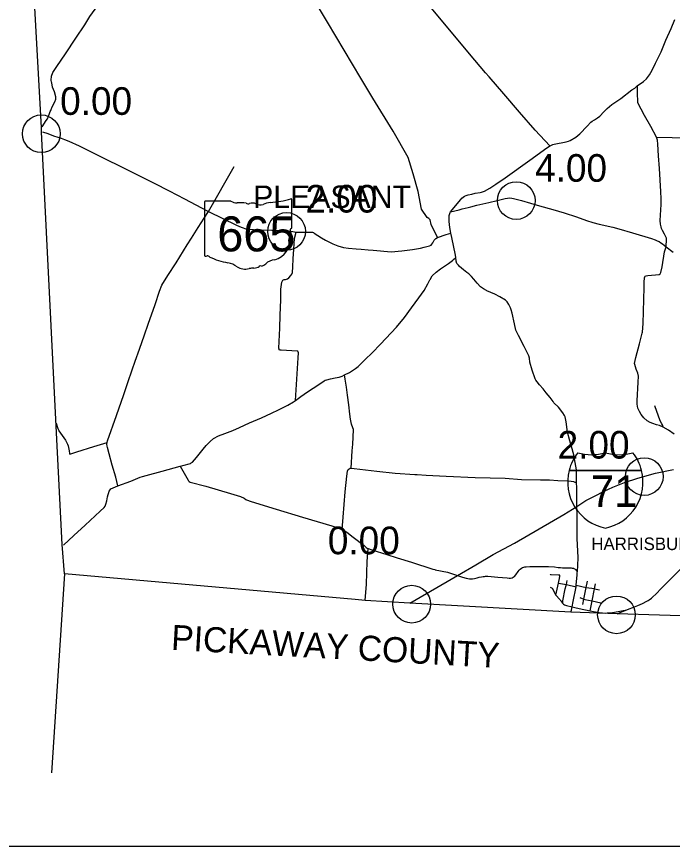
# Model space of a CAD drawing. Extents: x 1659811 to 1934326, y 644115 to 934867.
# Drawn here: x 1757686 to 1783780, y 650175 to 683194 of the extents above; entities that cross this region are included whole.
import ezdxf

# ---------------------------------------------------------------- set-up
doc = ezdxf.new("R2010")
doc.units = 0
for name, color, linetype in [('Default', 7, 'Continuous'), ('GM_X_Adjacent_County', 7, 'Continuous'), ('GM_X_Adjacent_County_Text', 7, 'Continuous'), ('GM_X_City_Street', 7, 'Continuous'), ('GM_X_Corporation_Text', 7, 'Continuous'), ('GM_X_County', 7, 'Continuous'), ('GM_X_County_Road', 7, 'Continuous'), ('GM_X_Interstate_Route', 7, 'Continuous'), ('GM_X_Interstate_Shield', 7, 'Continuous'), ('GM_X_State_Route', 7, 'Continuous'), ('GM_X_State_Shield', 7, 'Continuous'), ('GM_X_Township_Road', 7, 'Continuous'), ('GM_X_Township_Text', 7, 'Continuous'), ('GM_X_US_Route', 7, 'Continuous'), ('SC_Scratch1', 7, 'Continuous')]:
    doc.layers.add(name, color=color, linetype=linetype)

msp = doc.modelspace()

# ---------------------------------------------------------------- linework, layer by layer
at = {"layer": 'Default'}
for centre in [(1758669, 678534), (1758669, 678534), (1777567, 675872), (1768427, 674646), (1782661, 664892), (1773406, 659814), (1773406, 659814), (1781555, 659388), (1781555, 659388)]:
    msp.add_circle(centre, 750, dxfattribs=at)
at = {"layer": 'GM_X_Adjacent_County'}
msp.add_line((1759596, 661027), (1759070, 653104), dxfattribs=at)
at = {"layer": 'GM_X_City_Street'}
for points in [[(1779847, 661240), (1779853, 661239), (1779883, 661223), (1779909, 661206), (1779930, 661187), (1779979, 661133), (1780000, 661107)], [(1778915, 660978), (1778930, 660991), (1778950, 660994), (1779248, 660981), (1779262, 660981), (1779284, 660976)], [(1779263, 660711), (1779287, 660836), (1779305, 660926), (1779302, 660952), (1779284, 660976)], [(1779551, 660558), (1779561, 660595), (1779563, 660601), (1779594, 660760)], [(1779741, 659492), (1779762, 659575), (1779789, 659710), (1779832, 659924), (1779945, 660504), (1779955, 660564), (1779994, 660984), (1779997, 661054)], [(1780218, 659794), (1780262, 660012), (1780354, 660480), (1780407, 660730)], [(1778914, 660484), (1778995, 660444), (1779147, 660174), (1779301, 659998), (1779316, 659981)], [(1779147, 660174), (1779218, 660526), (1779253, 660654), (1779263, 660711)], [(1779253, 660654), (1779413, 660623)], [(1779413, 660623), (1779561, 660595), (1779945, 660504)], [(1779413, 659848), (1779419, 659887), (1779421, 659949), (1779516, 660426), (1779551, 660558)], [(1779955, 660564), (1780354, 660480), (1780676, 660432)], [(1780506, 659550), (1780588, 659944), (1780679, 660419)], [(1780676, 660432), (1780676, 660432), (1780681, 660430), (1780880, 660384)], [(1780679, 660419), (1780680, 660423), (1780681, 660430), (1780720, 660624)], [(1780101, 660073), (1780262, 660012), (1780292, 660006)], [(1779316, 659981), (1779328, 659966), (1779352, 659929), (1779378, 659888), (1779413, 659848)], [(1779413, 659848), (1779453, 659809), (1779488, 659785), (1779561, 659760), (1779789, 659710)], [(1780292, 660006), (1780588, 659944), (1780937, 659869)], [(1779789, 659710), (1779892, 659678), (1780069, 659640), (1780506, 659550), (1780854, 659487), (1780872, 659483)]]:
    msp.add_lwpolyline(points, dxfattribs=at)
at = {"layer": 'GM_X_County'}
msp.add_lwpolyline([(1784956, 659328), (1781576, 659434), (1779741, 659492), (1773339, 659850), (1771560, 659962), (1771157, 659994), (1759596, 661027), (1759497, 662188), (1759258, 666902), (1758681, 678614), (1758672, 678766), (1758400, 683790), (1758170, 688397), (1758072, 690399), (1757841, 694414), (1757825, 694698), (1757564, 699226), (1758151, 699596), (1759102, 700215)], dxfattribs=at)
at = {"layer": 'GM_X_County_Road'}
for points in [[(1759077, 680590), (1759061, 680668), (1759078, 680818), (1759131, 680968), (1759287, 681203), (1759631, 681711), (1760047, 682335), (1760404, 682872), (1760596, 683193), (1760806, 683496), (1760873, 683608), (1761094, 683872), (1761429, 684371), (1761902, 685082), (1762236, 685589), (1762361, 685777), (1762710, 686270), (1762844, 686434), (1763167, 686851), (1763522, 687306), (1763867, 687757), (1764291, 688315), (1764315, 688347)], [(1778904, 678047), (1778314, 678671), (1777693, 679394), (1777072, 680120), (1776484, 680798), (1776345, 680960), (1775913, 681464), (1774048, 683702), (1773810, 683978), (1773735, 684084)], [(1774956, 675429), (1775362, 675913), (1775404, 675965), (1775460, 676012), (1775514, 676048), (1775572, 676079), (1775656, 676108), (1775793, 676134), (1775936, 676163), (1776130, 676195), (1776187, 676207), (1776227, 676216), (1776304, 676244), (1776516, 676373), (1776754, 676520), (1777127, 676778), (1778110, 677485), (1778787, 677975), (1778847, 678015), (1778904, 678047), (1778937, 678067), (1778976, 678084), (1779027, 678103), (1779075, 678117), (1779556, 678216), (1779642, 678244), (1779710, 678267), (1779941, 678398), (1780096, 678528), (1780393, 678836), (1780538, 679000), (1780582, 679037), (1780675, 679091), (1780795, 679160), (1780886, 679237), (1781055, 679404), (1781184, 679531), (1781374, 679692), (1781486, 679771), (1781728, 679931), (1782163, 680280), (1782279, 680349), (1782391, 680450), (1782493, 680516), (1782627, 680609), (1782752, 680718), (1782868, 680877), (1782977, 681061), (1783111, 681340), (1783339, 681797), (1783524, 682256), (1783728, 682725), (1783880, 683080)], [(1759063, 679504), (1759105, 679598), (1759208, 679807), (1759243, 679915), (1759244, 680001), (1759197, 680198), (1759119, 680391), (1759084, 680555), (1759077, 680590)], [(1783844, 666582), (1783619, 666732), (1783419, 666860), (1783270, 666922), (1783149, 666951), (1783002, 666997), (1782890, 667046), (1782780, 667109), (1782641, 667230), (1782535, 667360), (1782467, 667486), (1782408, 667615), (1782384, 667769), (1782377, 667901), (1782412, 668652), (1782429, 668886), (1782404, 669000), (1782343, 669165), (1782281, 669354), (1782273, 669384), (1782325, 669630), (1782473, 670172), (1782582, 670601), (1782588, 670635), (1782611, 670984), (1782644, 671937), (1782659, 672414), (1782657, 672628), (1782664, 672804), (1782683, 672840), (1782701, 672870), (1782735, 672884), (1782799, 672895), (1783258, 672938), (1783298, 672959), (1783324, 673007), (1783374, 673235), (1783468, 673837), (1783535, 674036), (1783550, 674333), (1783542, 674374), (1783468, 674540), (1783387, 674689), (1783347, 674762), (1783328, 674832), (1783304, 674932), (1783299, 675075), (1783336, 675721), (1783338, 675938), (1783324, 676240), (1783261, 677156), (1783230, 677651), (1783198, 678124), (1783187, 678273), (1783142, 678403), (1782923, 678824), (1782676, 679262), (1782411, 679769), (1782409, 679811), (1782392, 680130), (1782391, 680450)], [(1758707, 678813), (1758861, 679055), (1758919, 679123), (1758993, 679335), (1759023, 679416), (1759045, 679464), (1759063, 679504)], [(1783142, 678403), (1783772, 678383), (1783773, 678383)], [(1783773, 678383), (1785029, 678344), (1785034, 678343), (1785035, 678343)], [(1761718, 664522), (1761629, 664869), (1761494, 665341), (1761375, 665791), (1761303, 666042), (1761289, 666098), (1761282, 666179), (1761289, 666249), (1761307, 666319), (1761667, 667325), (1761951, 668157), (1762115, 668630), (1762282, 669135), (1762409, 669489), (1762581, 669962), (1762769, 670526), (1762924, 670951), (1763200, 671744), (1763378, 672275), (1763468, 672511), (1763705, 672898), (1764033, 673400), (1764187, 673633), (1764477, 674115), (1764641, 674378), (1764908, 674799), (1765145, 675172), (1765320, 675443)], [(1775143, 673702), (1775006, 674406), (1774965, 674582)], [(1776387, 672291), (1776262, 672357), (1776143, 672446), (1776006, 672587), (1775875, 672747), (1775780, 672854), (1775718, 672924), (1775682, 672955), (1775601, 673017), (1775473, 673119), (1775314, 673250), (1775264, 673305), (1775207, 673375), (1775170, 673458), (1775162, 673604), (1775143, 673702)], [(1774127, 672717), (1774135, 672735), (1774225, 672873), (1774380, 673020), (1774555, 673162), (1774867, 673370), (1775024, 673487), (1775070, 673535), (1775162, 673604)], [(1764301, 665332), (1764301, 665332), (1764605, 665414), (1764637, 665432), (1764681, 665467), (1764841, 665654), (1765105, 665985), (1765231, 666134), (1765390, 666285), (1765525, 666400), (1765726, 666517), (1765965, 666611), (1766290, 666724), (1766553, 666846), (1766958, 667023), (1767424, 667224), (1767830, 667409), (1768105, 667551), (1768475, 667728), (1768710, 667866), (1768782, 667924), (1768990, 668078), (1769267, 668258), (1769708, 668551), (1769929, 668698), (1769969, 668723), (1770035, 668747), (1770182, 668782), (1770362, 668814), (1770522, 668849), (1770641, 668890), (1770737, 668933), (1770926, 669032), (1771171, 669190), (1771276, 669273), (1771560, 669549), (1771828, 669820), (1772171, 670165), (1772801, 670835), (1773122, 671225), (1773401, 671599), (1773692, 672000), (1773906, 672294), (1774048, 672554), (1774113, 672689), (1774127, 672717)], [(1779970, 664753), (1779970, 664754), (1779968, 664903), (1779958, 665156), (1779916, 665455), (1779856, 665754), (1779767, 666089), (1779704, 666310), (1779605, 666661), (1779588, 666760), (1779552, 667071), (1779533, 667201), (1779517, 667271), (1779492, 667327), (1779415, 667432), (1779242, 667654), (1779065, 667828), (1779034, 667876), (1778917, 668033), (1778760, 668219), (1778633, 668388), (1778498, 668548), (1778395, 668665), (1778341, 668727), (1778320, 668774), (1778204, 669129), (1778102, 669437), (1778095, 669601), (1778068, 669689), (1777883, 670067), (1777658, 670508), (1777579, 670661), (1777547, 670717), (1777497, 670964), (1777408, 671388), (1777367, 671520), (1777338, 671600), (1777278, 671733), (1777201, 671850), (1777142, 671913), (1776909, 672047), (1776709, 672149), (1776398, 672285), (1776389, 672290), (1776387, 672291)], [(1759547, 662165), (1759958, 662552), (1760412, 662957), (1761016, 663510), (1761167, 663661), (1761210, 663716), (1761240, 663796), (1761273, 663926), (1761307, 664090), (1761374, 664310), (1761405, 664366), (1761441, 664402), (1761529, 664445), (1761718, 664522), (1762230, 664712), (1762605, 664861), (1762694, 664895), (1762844, 664931), (1763478, 665102), (1764200, 665305), (1764301, 665332)], [(1764200, 665305), (1764508, 664749), (1764532, 664717), (1764549, 664699), (1764595, 664670), (1765211, 664507), (1766199, 664214), (1766592, 664095), (1766738, 664031), (1766806, 663977), (1766832, 663961), (1767023, 663901), (1768012, 663600), (1769058, 663279), (1770224, 662926), (1770486, 662848), (1770574, 662819), (1770642, 662787), (1770716, 662746), (1770829, 662675), (1771082, 662480), (1771512, 662142), (1771595, 662069), (1771631, 662047), (1771673, 662023), (1771823, 661973), (1772416, 661788), (1772823, 661656), (1773396, 661485), (1774251, 661212), (1774330, 661187)], [(1779992, 662480), (1779997, 663084), (1779995, 663356), (1779983, 663706), (1779979, 664192), (1779975, 664462), (1779970, 664647), (1779970, 664753)], [(1780000, 661107), (1780016, 661353), (1780029, 661677), (1779992, 662426), (1779992, 662464), (1779992, 662480)], [(1774330, 661187), (1774345, 661182), (1774826, 661093), (1775224, 660950), (1775426, 660892), (1775570, 660850)], [(1775570, 660850), (1775573, 660849), (1775645, 660831), (1775702, 660823), (1775752, 660820), (1775821, 660824), (1775899, 660840), (1776014, 660865), (1776093, 660882), (1776188, 660900), (1776247, 660912), (1776301, 660920), (1776345, 660924), (1776376, 660926), (1776437, 660926), (1776574, 660914), (1776830, 660891), (1777209, 660855), (1777290, 660850), (1777340, 660853), (1777402, 660866), (1777444, 660886), (1777493, 660920), (1777545, 660976), (1777644, 661113), (1777682, 661165), (1777719, 661203), (1777770, 661242), (1777821, 661270), (1777865, 661289), (1777912, 661301), (1777957, 661305), (1778112, 661307), (1778614, 661313), (1778735, 661315), (1778852, 661310), (1779083, 661293), (1779238, 661278), (1779326, 661271), (1779401, 661265), (1779473, 661263), (1779690, 661259), (1779718, 661258), (1779746, 661257)], [(1779746, 661257), (1779747, 661257), (1779794, 661251), (1779825, 661246), (1779847, 661240)], [(1779997, 661054), (1780000, 661107), (1780000, 661107)], [(1780872, 659483), (1780936, 659470), (1781001, 659463), (1781105, 659460), (1781183, 659463), (1781304, 659472), (1781396, 659484), (1781481, 659498), (1781967, 659586)]]:
    msp.add_lwpolyline(points, dxfattribs=at)
at = {"layer": 'GM_X_Interstate_Route'}
msp.add_lwpolyline([(1773339, 659850), (1775224, 660950), (1775957, 661376), (1776652, 661789), (1777498, 662236), (1779457, 663388), (1779983, 663706), (1780338, 663933), (1780676, 664112), (1781059, 664311), (1781412, 664474), (1781875, 664650), (1782399, 664828), (1783114, 665027), (1783830, 665175)], dxfattribs=at)
at = {"layer": 'GM_X_Interstate_Shield'}
for p, q in [((1779669, 665137), (1782554, 665137)), ((1782554, 665137), (1779669, 665137)), ((1782554, 665137), (1779669, 665137))]:
    msp.add_line(p, q, dxfattribs=at)
for centre, start, end in [((1781487, 664677), 141.669, 165.8066), ((1780564, 667633), 253.0091, 286.9909), ((1781659, 667633), 253.0091, 286.9909), ((1780737, 664677), 14.1934, 38.331), ((1781487, 664677), 165.8066, 258.463), ((1780737, 664677), 281.537, 14.1934)]:
    msp.add_arc(centre, 1875, start, end, dxfattribs=at)
at = {"layer": 'GM_X_State_Route'}
for points in [[(1758718, 678605), (1758924, 678536), (1759155, 678456), (1759328, 678400), (1759455, 678358), (1759590, 678309), (1759762, 678235), (1759915, 678170), (1760033, 678118), (1760182, 678048), (1760356, 677962), (1761185, 677549), (1761857, 677219), (1762607, 676839), (1763166, 676560), (1763750, 676259), (1764361, 675943), (1765045, 675589), (1765320, 675443), (1766432, 674900), (1766528, 674860), (1766624, 674819), (1766707, 674783), (1766766, 674760), (1766836, 674741), (1766930, 674733), (1767316, 674714), (1767839, 674697), (1768338, 674685), (1768516, 674670), (1768673, 674646), (1768805, 674613), (1768981, 674615), (1769337, 674616), (1769425, 674616), (1769459, 674611), (1769494, 674600), (1769524, 674583), (1769666, 674488), (1769814, 674389), (1769977, 674293), (1770036, 674265)], [(1776813, 675876), (1777131, 675954), (1777214, 675975), (1777318, 675984), (1777389, 675973), (1777453, 675960), (1777771, 675870), (1778493, 675666), (1779017, 675513)], [(1771677, 673914), (1771877, 673898), (1772593, 673840), (1773013, 673876), (1773444, 673930), (1773760, 673979), (1773909, 674015), (1774111, 674070), (1774175, 674101), (1774214, 674140), (1774245, 674198), (1774272, 674244), (1774303, 674298), (1774331, 674330), (1774372, 674364), (1774429, 674407), (1774779, 674519), (1774965, 674582), (1774929, 674798), (1774892, 675044), (1774891, 675067), (1774898, 675281), (1774939, 675401), (1774956, 675429), (1775298, 675511), (1775413, 675541), (1775530, 675569), (1775648, 675596), (1775766, 675623), (1775997, 675685), (1776236, 675741), (1776474, 675794), (1776813, 675876)], [(1779017, 675513), (1779470, 675381), (1779964, 675221), (1780368, 675082), (1780611, 675007), (1780865, 674940), (1781405, 674816), (1781645, 674748), (1782195, 674586), (1782945, 674365), (1783098, 674311), (1783174, 674276), (1783251, 674240), (1783326, 674193), (1783381, 674155), (1783451, 674103), (1783535, 674036), (1783804, 673822)], [(1770036, 674265), (1770273, 674153), (1770470, 674076), (1770695, 674012), (1770898, 673985), (1771197, 673953), (1771395, 673937), (1771677, 673914)]]:
    msp.add_lwpolyline(points, dxfattribs=at)
at = {"layer": 'GM_X_State_Shield'}
for p, q in [((1765162, 675817), (1765162, 673703)), ((1766216, 675853), (1765196, 675853)), ((1768642, 674800), (1768642, 675905)), ((1768642, 674800), (1768642, 674800))]:
    msp.add_line(p, q, dxfattribs=at)
for centre, major_axis, start_param, end_param in [((1767403, 678734), (3691, 0), 4.814394, 5.042369), ((1768604, 675910), (38.7, 0), 6.141152, 7.989035), ((1765202, 675821), (40.3, 0), 1.712693, 3.28349), ((1766458, 676098), (391, 0), 4.042523, 4.731795), ((1766588, 674667), (1404, 0), 1.404758, 1.657858), ((1766907, 675832), (113, 0), 3.836095, 5.185415), ((1767072, 675588), (235, 0), 0.950623, 2.079405), ((1767375, 675923), (282, 0), 4.081561, 5.145723), ((1767873, 675208), (743, 0), 1.699011, 2.107814), ((1768633, 674719), (60, 0), 1.883978, 3.671073), ((1768252, 674579), (360, 0), 5.934695, 6.695948), ((1768601, 674796), (41.5, 0), 5.05454, 6.418171), ((1767609, 674197), (923, 0), 5.101752, 6.440018), ((1768781, 674337), (262, 0), 2.387724, 3.262537), ((1765202, 673699), (40.7, 0), 3.00124, 4.508301), ((1765208, 673915), (310, 0), 4.665946, 4.897461), ((1765272, 673581), (112, 0), 0.519207, 1.627899), ((1766685, 675480), (2665, 0), 4.195997, 4.488961), ((1765890, 672754), (834, 0), 0.823519, 1.323587), ((1767392, 673208), (79.4, 0), 1.147584, 2.315152), ((1767358, 673499), (298, 0), 4.937069, 5.64225), ((1767999, 673110), (506, 0), 1.647645, 2.488434), ((1766792, 673571), (529, 0), 4.026481, 4.996735), ((1767098, 672840), (435, 0), 1.495662, 1.94098), ((1767137, 673413), (282, 0), 4.691044, 5.507374)]:
    msp.add_ellipse(centre, major_axis=major_axis, ratio=0.8, start_param=start_param, end_param=end_param, dxfattribs=at)
at = {"layer": 'GM_X_Township_Road'}
for points in [[(1774429, 674407), (1774188, 674926), (1774139, 675101), (1774091, 675155), (1774025, 675200), (1773798, 675535), (1773663, 676229), (1773462, 676936), (1773264, 677586), (1772665, 678633), (1771860, 679950), (1771386, 680739), (1770061, 682979), (1769620, 683702), (1769410, 684045), (1769171, 684488)], [(1765320, 675443), (1766343, 677226)], [(1768782, 667924), (1768885, 669618), (1768902, 669820), (1768894, 669852), (1768879, 669876), (1768851, 669884), (1768219, 669922), (1768169, 669926), (1768139, 669936), (1768127, 669957), (1768117, 669999), (1768155, 670792), (1768179, 671312), (1768197, 671923), (1768200, 672352), (1768222, 672528), (1768242, 672630), (1768285, 672702), (1768327, 672737), (1768389, 672737), (1768461, 672760), (1768520, 672800), (1768603, 672892), (1768639, 672943), (1768659, 673013), (1768677, 673235), (1768691, 673554), (1768716, 673942), (1768745, 674359), (1768805, 674613)], [(1770996, 665230), (1771039, 665921), (1771065, 666186), (1771077, 666462), (1771093, 666764), (1771068, 666837), (1771009, 666979), (1770968, 667178), (1770940, 667377), (1770901, 667750), (1770849, 668125), (1770808, 668454), (1770760, 668767), (1770737, 668933)], [(1783419, 666860), (1783397, 666917), (1783353, 666983), (1783295, 667108), (1783084, 667706)], [(1759265, 667013), (1759325, 666804), (1759328, 666798)], [(1759328, 666798), (1759369, 666719), (1759372, 666715), (1759626, 666342), (1759664, 666282), (1759709, 666178)], [(1759709, 666178), (1759734, 666118), (1759737, 666113), (1759777, 665920), (1759792, 665810), (1759798, 665786), (1760083, 665878), (1760753, 666081), (1761289, 666249)], [(1770642, 662787), (1770675, 663273), (1770765, 664287), (1770830, 664907), (1770857, 665105), (1770884, 665169), (1770914, 665205), (1770952, 665225), (1770996, 665230), (1771116, 665211), (1772026, 665102), (1772750, 665027), (1773538, 664969), (1773618, 664968), (1773976, 664951), (1774772, 664906), (1775927, 664855), (1777126, 664825), (1777776, 664781), (1778534, 664755), (1778892, 664756), (1779224, 664731), (1779613, 664718), (1779753, 664707), (1779841, 664692), (1779897, 664671), (1779913, 664666), (1779970, 664647)], [(1771560, 659962), (1771611, 660607), (1771641, 661518), (1771673, 662023)]]:
    msp.add_lwpolyline(points, dxfattribs=at)
at = {"layer": 'GM_X_US_Route'}
for points in [[(1782818, 659962), (1782858, 659989), (1782950, 660058), (1783174, 660262), (1783295, 660401), (1784050, 661158), (1784789, 661898), (1785521, 662721), (1785931, 663218), (1786031, 663343), (1786129, 663449), (1786199, 663506), (1786267, 663559), (1786382, 663639), (1786511, 663709), (1786630, 663762), (1786734, 663801), (1786844, 663844), (1787022, 663911), (1787043, 663919)], [(1782064, 659623), (1782208, 659678), (1782405, 659767), (1782588, 659843), (1782767, 659928), (1782818, 659962)], [(1781576, 659434), (1781708, 659481), (1781967, 659586), (1782064, 659623)]]:
    msp.add_lwpolyline(points, dxfattribs=at)
at = {"layer": 'SC_Scratch1'}
msp.add_lwpolyline([(1730291, 784675), (1926541, 784675), (1926541, 650175), (1730291, 650175)], close=True, dxfattribs=at)

# ---------------------------------------------------------------- texts
at = {"layer": 'Default'}
for s, p in [('0.00', (1759419, 679284)), ('4.00', (1778317, 676622)), ('2.00', (1769177, 675396)), ('2.00', (1779212, 665606)), ('0.00', (1770070, 661800))]:
    msp.add_text(s, height=1100, dxfattribs=at).set_placement(p)
at = {"layer": 'GM_X_Adjacent_County_Text'}
msp.add_text('PICKAWAY COUNTY', height=1000, rotation=356.8216, dxfattribs=at).set_placement((1763818, 657997))
at = {"layer": 'GM_X_Corporation_Text'}
msp.add_text('HARRISBURG', height=500, rotation=0, dxfattribs=at).set_placement((1780555, 661965))
at = {"layer": 'GM_X_Interstate_Shield'}
msp.add_text('71', height=1250, dxfattribs=at).set_placement((1780534, 663684))
at = {"layer": 'GM_X_State_Shield'}
msp.add_text('665', height=1392.2, dxfattribs=at).set_placement((1765672, 673852))
at = {"layer": 'GM_X_Township_Text'}
msp.add_text('PLEASANT', height=900, rotation=0, dxfattribs=at).set_placement((1767095, 675573))

doc.saveas('drawing.dxf')
